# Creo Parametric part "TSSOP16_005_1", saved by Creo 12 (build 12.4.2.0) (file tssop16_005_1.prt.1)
Units: Custom; MM, KILOGRAM, SECS

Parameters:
  PTC_WM_ITERATION = "0"
  PTC_WM_VERSION = "-.0"
  PTC_WM_LIFECYCLE_STATE = "In Work"
  PTC_WM_LIFECYCLE = "MO_CADDocument"
  PTC_WM_CREATED_BY = "Maximilian Roepper (Z0017RMS: MO)"
  PTC_WM_CREATED_ON = "18-Sep-26 11:36:42 AM"
  PTC_WM_MODIFIED_BY = "Maximilian Roepper (Z0017RMS: MO)"
  PTC_WM_MODIFIED_ON = "18-Sep-26 11:36:46 AM"
  PDMLINKNUMBER = "PDM000071455173"
  PTC_WM_NAME = "tssop16_005_1.prt"
  PTC_WM_NUMBER = "PDM000071455173"

Other parameters: WEIGHT, WEIGHT_FACTOR, WEIGHT_ADD, _MASS_TEMP, _DIFF_TEMP, MC_ERRORS, SUPPLIER

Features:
  1. coordinate system
  2. datum plane "PRT_YZ"
  3. datum plane "PRT_XY"
  4. datum plane "PRT_XZ"
  5. coordinate system
  6. datum axis
  7. datum axis
  8. datum axis
  9. coordinate system
  10. imported feature

Other named items: PRT, SIEMENS_MO, DRW_VIEW_ORG, PRT_X, PRT_Y, PRT_Z, CS0, ROUGH_GROB

Layers: 00_STD_CSYS-KSYS, 01_STD_PLANES-EBENEN, 02_STD_AXES-ACHSEN, 03_STD_CSYS-KSYS, 24_IMPORT_FEAT-IMPORT_KE

Surfaces: 14 plane, 8 cylinder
